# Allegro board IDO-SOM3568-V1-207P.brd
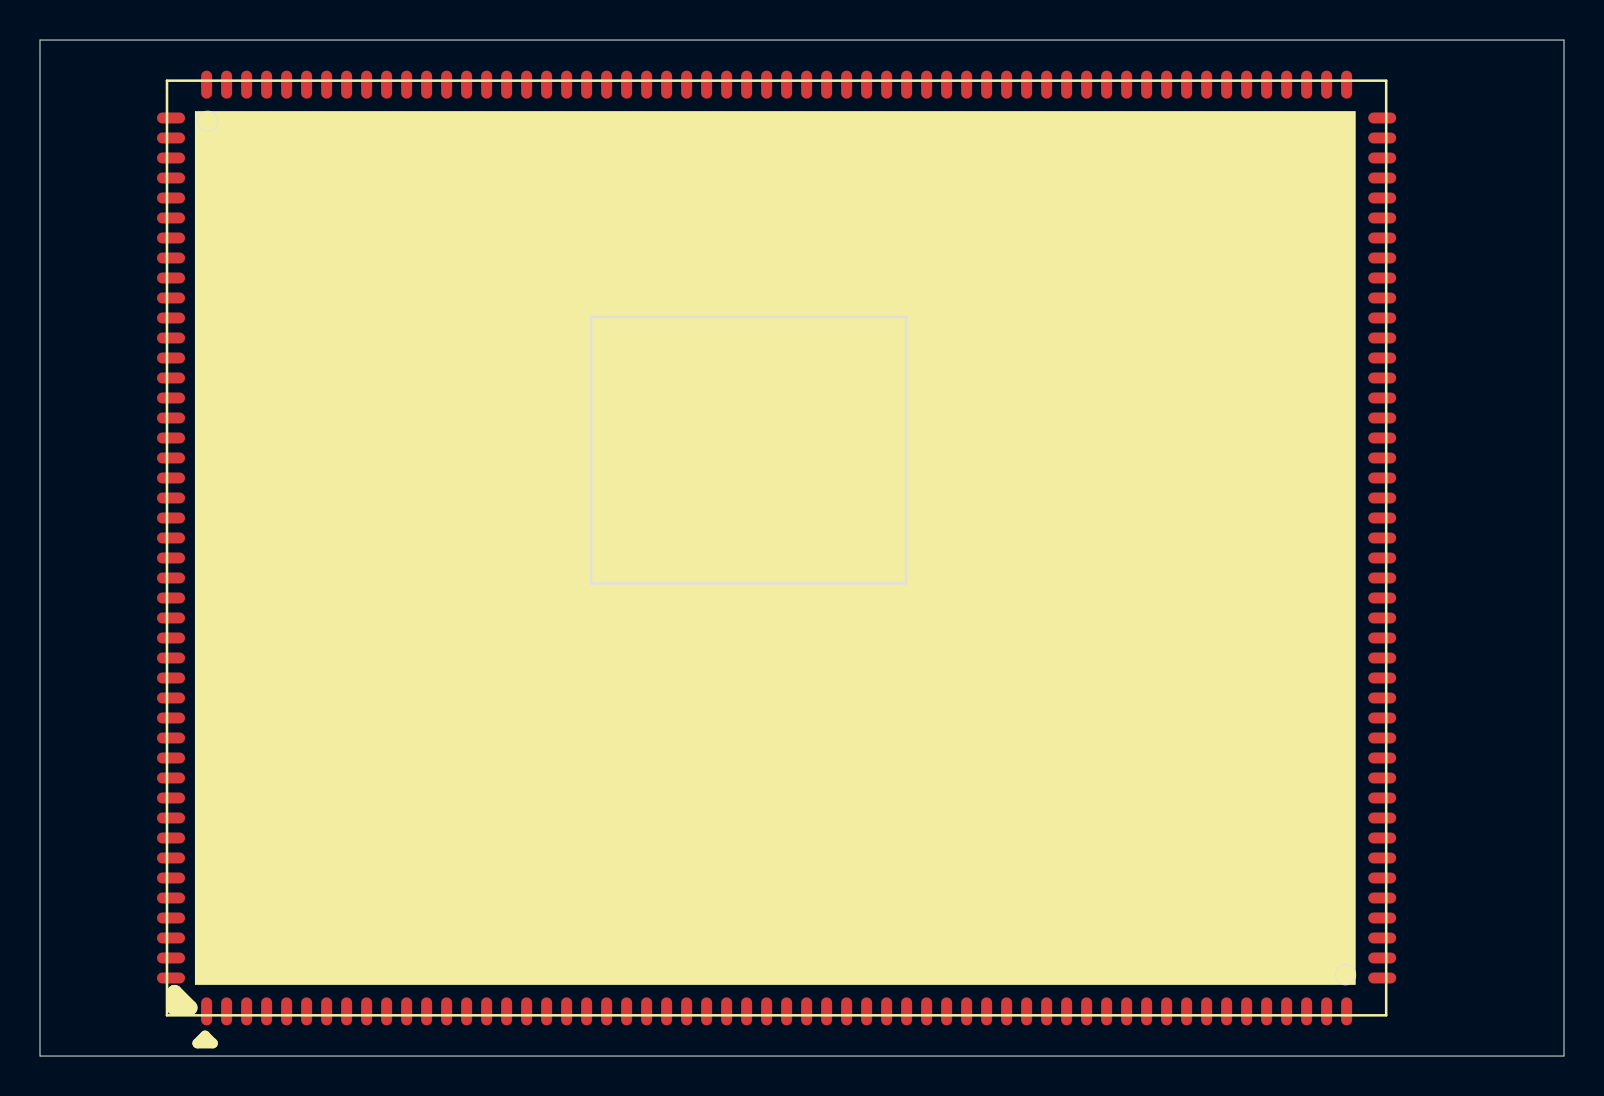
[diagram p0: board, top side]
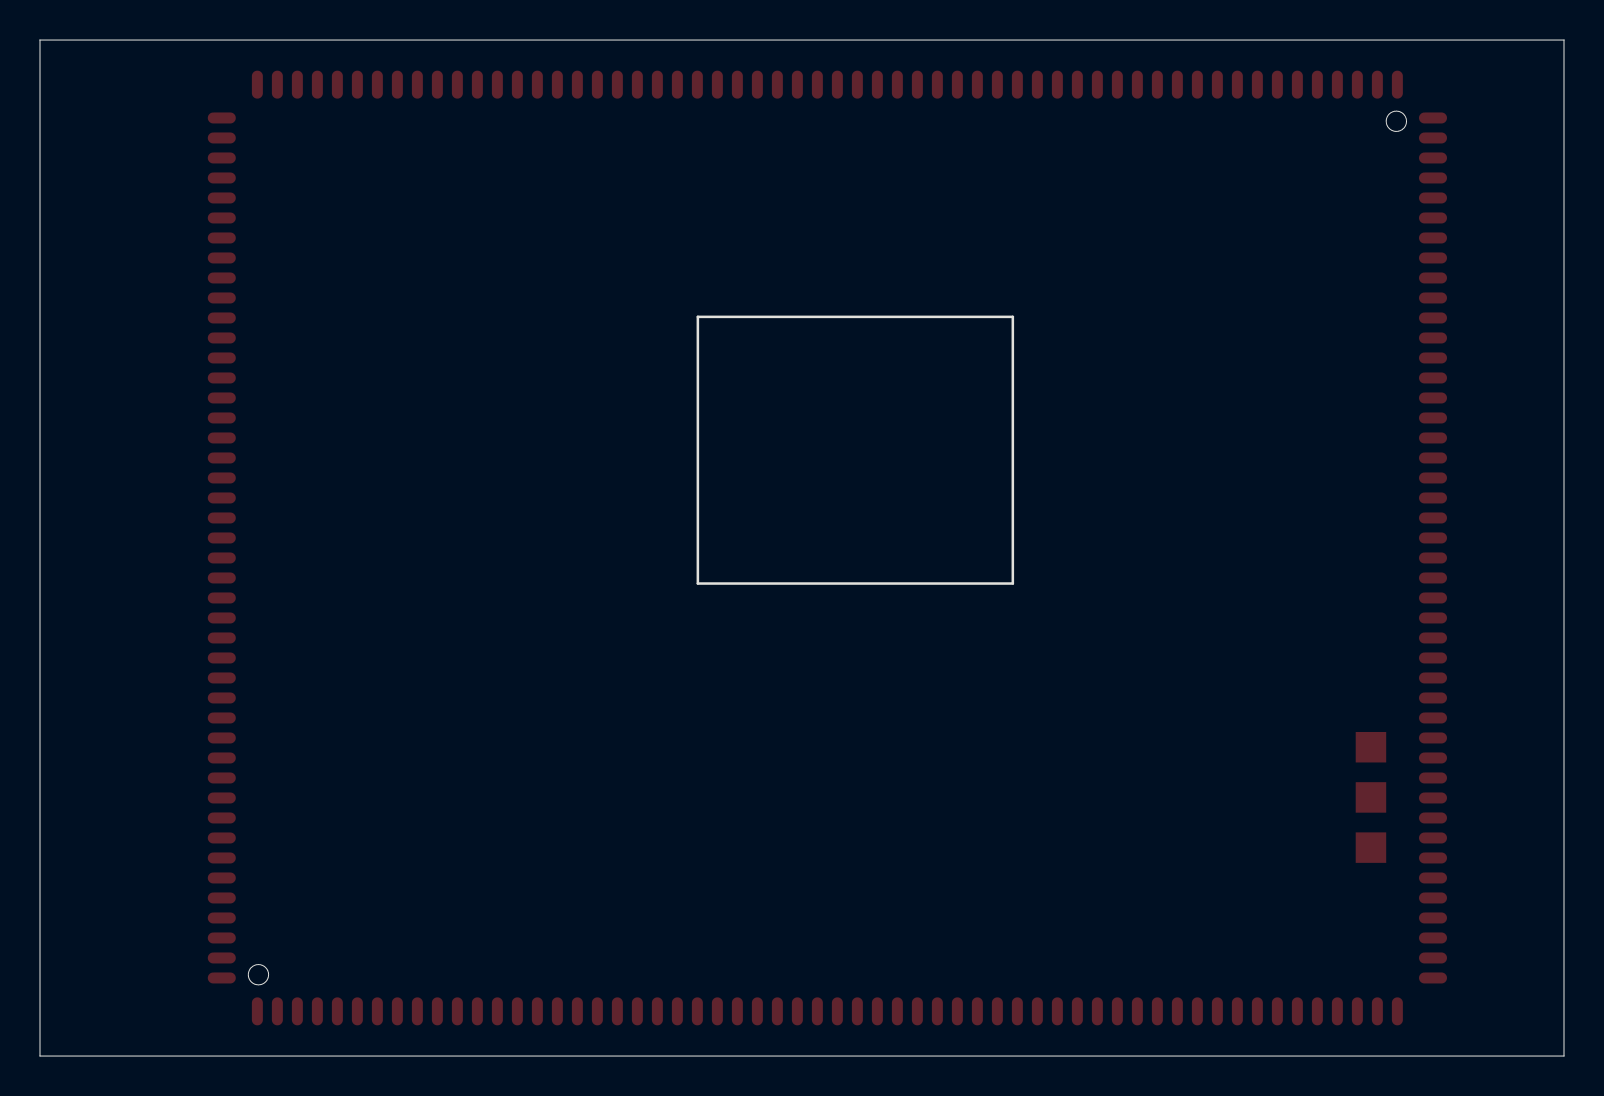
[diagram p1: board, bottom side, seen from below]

Outline 76.2 x 50.8 mm; copper layers: TOP, VCC, GND, BOTTOM. Coordinates in mm from the lower left corner of the outline.
Outline path: 0,50.8 0,0 76.2,0 76.2,50.8 0,50.8

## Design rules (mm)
net group DIFFPAIR0: nets HDMI_TX_D2N HDMI_TX_D2P
net group DIFFPAIR1: nets HDMI_TX_D2N_ HDMI_TX_D2P_
net group DIFFPAIR2: nets HDMI_TX_D1N_ HDMI_TX_D1P_
net group DIFFPAIR3: nets HDMI_TX_D1N HDMI_TX_D1P
net group DIFFPAIR4: nets HDMI_TX_D0N_ HDMI_TX_D0P_
net group DIFFPAIR5: nets HDMI_TX_D0N HDMI_TX_D0P
net group DIFFPAIR6: nets HDMI_TX_CLKN_ HDMI_TX_CLKP_
net group DIFFPAIR7: nets HDMI_TX_CLKN HDMI_TX_CLKP
net group DIFFPAIR8: nets USB2_HOST3_DM_ USB2_HOST3_DP_
net group DIFFPAIR9: nets FE2.1_DM1_ FE2.1_DP1_
net group DIFFPAIR10: nets FE2.1_DM1 FE2.1_DP1
net group DIFFPAIR11: nets USB2_HOST3_DM USB2_HOST3_DP
net group DIFFPAIR12: nets FE2.1_DM2_ FE2.1_DP2_
net group DIFFPAIR13: nets FE2.1_DM3_ FE2.1_DP3_
net group DIFFPAIR14: nets FE2.1_DM2 FE2.1_DP2
net group DIFFPAIR15: nets FE2.1_DM3 FE2.1_DP3
net group DIFFPAIR16: nets LVDS0_D0N LVDS0_D0P
net group DIFFPAIR17: nets LVDS0_D1N LVDS0_D1P
net group DIFFPAIR18: nets LVDS0_D2N LVDS0_D2P
net group DIFFPAIR19: nets LVDS0_CLKN LVDS0_CLKP
net group DIFFPAIR20: nets LVDS0_D3N LVDS0_D3P
net group DIFFPAIR21: nets LVDS1_D0N LVDS1_D0P
net group DIFFPAIR22: nets LVDS1_D1N LVDS1_D1P
net group DIFFPAIR23: nets LVDS1_D2N LVDS1_D2P
net group DIFFPAIR24: nets LVDS1_CLKN LVDS1_CLKP
net group DIFFPAIR25: nets LVDS1_D3N LVDS1_D3P
net group DIFFPAIR26: nets EDP_TX_D3N EDP_TX_D3P
net group DIFFPAIR27: nets EDP_TX_D3N_ EDP_TX_D3P_
net group DIFFPAIR28: nets EDP_TX_AUXN EDP_TX_AUXP
net group DIFFPAIR29: nets EDP_TX_AUXN_ EDP_TX_AUXP_
net group DIFFPAIR30: nets EDP_TX_D2N EDP_TX_D2P
net group DIFFPAIR31: nets EDP_TX_D2N_ EDP_TX_D2P_
net group DIFFPAIR32: nets EDP_TX_D1N EDP_TX_D1P
net group DIFFPAIR33: nets EDP_TX_D1N_ EDP_TX_D1P_
net group DIFFPAIR34: nets EDP_TX_D0N EDP_TX_D0P
net group DIFFPAIR35: nets EDP_TX_D0N_ EDP_TX_D0P_
net group DIFFPAIR36: nets USB3_HOST1_SSRXN_ USB3_HOST1_SSRXP_
net group DIFFPAIR37: nets USB3_HOST1_DM_ USB3_HOST1_DP_
net group DIFFPAIR38: nets USB3_OTG0_DM_ USB3_OTG0_DP_
net group DIFFPAIR39: nets USB3_OTG0_SSTXN_ USB3_OTG0_SSTXP_
net group DIFFPAIR40: nets USB3_HOST1_SSTXN_ USB3_HOST1_SSTXP_
net group DIFFPAIR41: nets USB3_HOST1_SSTXN USB3_HOST1_SSTXP
net group DIFFPAIR42: nets SATA1_TXN SATA1_TXP
net group DIFFPAIR43: nets USB3_OTG0_SSTXN USB3_OTG0_SSTXP
net group DIFFPAIR44: nets USB3_OTG0_DM USB3_OTG0_DP
net group DIFFPAIR45: nets USB3_HOST1_DM USB3_HOST1_DP
net group DIFFPAIR46: nets SATA1_RXN SATA1_RXP
net group DIFFPAIR47: nets USB3_HOST1_SSRXN USB3_HOST1_SSRXP
net group DIFFPAIR48: nets USB3_OTG0_SSRXN_ USB3_OTG0_SSRXP_
net group DIFFPAIR49: nets USB3_OTG0_SSRXN USB3_OTG0_SSRXP
net group DIFFPAIR50: nets FE2.1_DM5_ FE2.1_DP5_
net group DIFFPAIR51: nets FE2.1_DM5 FE2.1_DP5
net group DIFFPAIR52: nets FE2.1_DM6_ FE2.1_DP6_
net group DIFFPAIR53: nets FE2.1_DM6 FE2.1_DP6
net group DIFFPAIR54: nets FE2.1_DM4_ FE2.1_DP4_
net group DIFFPAIR55: nets FE2.1_DM4 FE2.1_DP4
net group DIFFPAIR56: nets MIPI_DSI_TX0_D3N_ MIPI_DSI_TX0_D3P_
net group DIFFPAIR57: nets MIPI_DSI_TX0_D2N_ MIPI_DSI_TX0_D2P_
net group DIFFPAIR58: nets MIPI_DSI_TX0_D3N MIPI_DSI_TX0_D3P
net group DIFFPAIR59: nets MIPI_DSI_TX0_D2N MIPI_DSI_TX0_D2P
net group DIFFPAIR60: nets MIPI_DSI_TX0_CLKN_ MIPI_DSI_TX0_CLKP_
net group DIFFPAIR61: nets MIPI_DSI_TX0_D1N_ MIPI_DSI_TX0_D1P_
net group DIFFPAIR62: nets MIPI_DSI_TX0_D1N MIPI_DSI_TX0_D1P
net group DIFFPAIR63: nets MIPI_DSI_TX0_CLKN MIPI_DSI_TX0_CLKP
net group DIFFPAIR64: nets MIPI_DSI_TX1_D3N MIPI_DSI_TX1_D3P
net group DIFFPAIR65: nets MIPI_DSI_TX1_D2N MIPI_DSI_TX1_D2P
net group DIFFPAIR66: nets MIPI_DSI_TX1_CLKN MIPI_DSI_TX1_CLKP
net group DIFFPAIR67: nets MIPI_DSI_TX1_D1N MIPI_DSI_TX1_D1P
net group DIFFPAIR68: nets MIPI_DSI_TX1_D0N MIPI_DSI_TX1_D0P
net group DIFFPAIR69: nets MIPI_DSI_TX0_D0N_ MIPI_DSI_TX0_D0P_
net group DIFFPAIR70: nets MIPI_DSI_TX0_D0N MIPI_DSI_TX0_D0P
net group DIFFPAIR71: nets USB2_HOST2_DM USB2_HOST2_DP
net group DIFFPAIR72: nets FE2.1_DM0 FE2.1_DP0
net group DIFFPAIR73: nets PCIE20_TXN PCIE20_TXP
net group DIFFPAIR74: nets PCIE20_RXN PCIE20_RXP
net group DIFFPAIR75: nets PCIE20_REFCLKN PCIE20_REFCLKP
net group DIFFPAIR76: nets PHY0_MDI3+ PHY0_MDI3-
net group DIFFPAIR77: nets PHY0_MDI2+ PHY0_MDI2-
net group DIFFPAIR78: nets PHY0_MDI1+ PHY0_MDI1-
net group DIFFPAIR79: nets LAN0_B+ LAN0_B-
net group DIFFPAIR80: nets LAN0_C+ LAN0_C-
net group DIFFPAIR81: nets LAN0_D+ LAN0_D-
net group DIFFPAIR82: nets LAN0_A+ LAN0_A-
net group DIFFPAIR83: nets PHY0_MDI0+ PHY0_MDI0-
net group DIFFPAIR84: nets PHY1_MDI0+ PHY1_MDI0-
net group DIFFPAIR85: nets LAN1_A+ LAN1_A-
net group DIFFPAIR86: nets LAN1_B+ LAN1_B-
net group DIFFPAIR87: nets PHY1_MDI1+ PHY1_MDI1-
net group DIFFPAIR88: nets LAN1_C+ LAN1_C-
net group DIFFPAIR89: nets PHY1_MDI2+ PHY1_MDI2-
net group DIFFPAIR90: nets PHY1_MDI3+ PHY1_MDI3-
net group DIFFPAIR91: nets LAN1_D+ LAN1_D-
net group DIFFPAIR92: nets FE2.1_DM7 FE2.1_DP7
net group DIFFPAIR93: nets FE2.1_DM7_ FE2.1_DP7_
net group DIFFPAIR96: nets REFCLKN_ REFCLKP_
net group DIFFPAIR97: nets VOLN VOLP
net group DIFFPAIR98: nets VORN VORP
net group DIFFPAIR99: nets MIPI_CSI_RX_D0N MIPI_CSI_RX_D0P
net group DIFFPAIR100: nets MIPI_CSI_RX_D1N MIPI_CSI_RX_D1P
net group DIFFPAIR101: nets MIPI_CSI_RX_D2N MIPI_CSI_RX_D2P
net group DIFFPAIR102: nets MIPI_CSI_RX_D3N MIPI_CSI_RX_D3P
net group DIFFPAIR103: nets MIPI_CSI_RX_CLK0N MIPI_CSI_RX_CLK0P
net group DIFFPAIR104: nets MIPI_CSI_D0N MIPI_CSI_D0P
net group DIFFPAIR105: nets MIPI_CSI_D1N MIPI_CSI_D1P
net group DIFFPAIR106: nets MIPI_CSI_D2N MIPI_CSI_D2P
net group DIFFPAIR107: nets MIPI_CSI_D3N MIPI_CSI_D3P
net group DIFFPAIR108: nets MIPI_CSI_CLKN MIPI_CSI_CLKP
net group DIFFPAIR109: nets PCIE20_RXN_ PCIE20_RXP_
net group DIFFPAIR110: nets PCIE20_TXN_ PCIE20_TXP_
net group PWR-20: nets VDD_RTC
net group SD-12: nets SD_CMD SD_D0 SD_D1 SD_D2 SD_D3

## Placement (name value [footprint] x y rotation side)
M5  IDO-SOM3568  [SOM3568-204P]  5.84 1.52 0 top

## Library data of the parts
M5 = MODE-204P_2

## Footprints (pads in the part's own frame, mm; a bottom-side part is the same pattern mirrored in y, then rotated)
SOM3568-204P
  oval 0.55x1.4 smd: 1(2.489,0.708) 2(3.489,0.708) 3(4.489,0.708) 4(5.489,0.708) 5(6.489,0.708) 6(7.489,0.708) 7(8.489,0.708) 8(9.489,0.708) 9(10.489,0.708) 10(11.489,0.708) 11(12.489,0.708) 12(13.489,0.708) 13(14.489,0.708) 14(15.489,0.708) 15(16.489,0.708) 16(17.489,0.708) 17(18.489,0.708) 18(19.489,0.708) 19(20.489,0.708) 20(21.489,0.708) 21(22.489,0.708) 22(23.489,0.708) 23(24.489,0.708) 24(25.489,0.708) 25(26.489,0.708) 26(27.489,0.708) 27(28.489,0.708) 28(29.489,0.708) 29(30.489,0.708) 30(31.489,0.708) 31(32.489,0.708) 32(33.489,0.708) 33(34.489,0.708) 34(35.489,0.708) 35(36.489,0.708) 36(37.489,0.708) 37(38.489,0.708) 38(39.489,0.708) 39(40.489,0.708) 40(41.489,0.708) 41(42.489,0.708) 42(43.489,0.708) 43(44.489,0.708) 44(45.489,0.708) 45(46.489,0.708) 46(47.489,0.708) 47(48.489,0.708) 48(49.489,0.708) 49(50.489,0.708) 50(51.489,0.708) 51(52.489,0.708) 52(53.489,0.708) 53(54.489,0.708) 54(55.489,0.708) 55(56.489,0.708) 56(57.489,0.708) 57(58.489,0.708) 58(59.489,0.708) 103(59.489,47.044) 104(58.489,47.044) 105(57.489,47.044) 106(56.489,47.044) 107(55.489,47.044) 108(54.489,47.044) 109(53.489,47.044) 110(52.489,47.044) 111(51.489,47.044) 112(50.489,47.044) 113(49.489,47.044) 114(48.489,47.044) 115(47.489,47.044) 116(46.489,47.044) 117(45.489,47.044) 118(44.489,47.044) 119(43.489,47.044) 120(42.489,47.044) 121(41.489,47.044) 122(40.489,47.044) 123(39.489,47.044) 124(38.489,47.044) 125(37.489,47.044) 126(36.489,47.044) 127(35.489,47.044) 128(34.489,47.044) 129(33.489,47.044) 130(32.489,47.044) 131(31.489,47.044) 132(30.489,47.044) 133(29.489,47.044) 134(28.489,47.044) 135(27.489,47.044) 136(26.489,47.044) 137(25.489,47.044) 138(24.489,47.044) 139(23.489,47.044) 140(22.489,47.044) 141(21.489,47.044) 142(20.489,47.044) 143(19.489,47.044) 144(18.489,47.044) 145(17.489,47.044) 146(16.489,47.044) 147(15.489,47.044) 148(14.489,47.044) 149(13.489,47.044) 150(12.489,47.044) 151(11.489,47.044) 152(10.489,47.044) 153(9.489,47.044) 154(8.489,47.044) 155(7.489,47.044) 156(6.489,47.044) 157(5.489,47.044) 158(4.489,47.044) 159(3.489,47.044) 160(2.489,47.044)
  oval 1.4x0.55 smd: 59(61.268,2.377) 60(61.268,3.377) 61(61.268,4.377) 62(61.268,5.377) 63(61.268,6.377) 64(61.268,7.377) 65(61.268,8.377) 66(61.268,9.377) 67(61.268,10.377) 68(61.268,11.377) 69(61.268,12.377) 70(61.268,13.377) 71(61.268,14.377) 72(61.268,15.377) 73(61.268,16.377) 74(61.268,17.377) 75(61.268,18.377) 76(61.268,19.377) 77(61.268,20.377) 78(61.268,21.377) 79(61.268,22.377) 80(61.268,23.377) 81(61.268,24.377) 82(61.268,25.377) 83(61.268,26.377) 84(61.268,27.377) 85(61.268,28.377) 86(61.268,29.377) 87(61.268,30.377) 88(61.268,31.377) 89(61.268,32.377) 90(61.268,33.377) 91(61.268,34.377) 92(61.268,35.377) 93(61.268,36.377) 94(61.268,37.377) 95(61.268,38.377) 96(61.268,39.377) 97(61.268,40.377) 98(61.268,41.377) 99(61.268,42.377) 100(61.268,43.377) 101(61.268,44.377) 102(61.268,45.377) 161(0.708,45.377) 162(0.708,44.377) 163(0.708,43.377) 164(0.708,42.377) 165(0.708,41.377) 166(0.708,40.377) 167(0.708,39.377) 168(0.708,38.377) 169(0.708,37.377) 170(0.708,36.377) 171(0.708,35.377) 172(0.708,34.377) 173(0.708,33.377) 174(0.708,32.377) 175(0.708,31.377) 176(0.708,30.377) 177(0.708,29.377) 178(0.708,28.377) 179(0.708,27.377) 180(0.708,26.377) 181(0.708,25.377) 182(0.708,24.377) 183(0.708,23.377) 184(0.708,22.377) 185(0.708,21.377) 186(0.708,20.377) 187(0.708,19.377) 188(0.708,18.377) 189(0.708,17.377) 190(0.708,16.377) 191(0.708,15.377) 192(0.708,14.377) 193(0.708,13.377) 194(0.708,12.377) 195(0.708,11.377) 196(0.708,10.377) 197(0.708,9.377) 198(0.708,8.377) 199(0.708,7.377) 200(0.708,6.377) 201(0.708,5.377) 202(0.708,4.377) 203(0.708,3.377) 204(0.708,2.377)
  rect 1.524x1.524 smd: 205(3.81,8.895) 206(3.81,11.405) 207(3.81,13.914)

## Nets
GND: M5.4(GND1) M5.5(GND2) M5.14(GND3) M5.38(GND4) M5.98(GND5) M5.105(GND6) M5.127(GND7) M5.152(GND8) M5.179(GND9) M5.194(GND10)
VCC3V3_SD: M5.69(VCC3V3_SD)
VCC5V0_SYS: M5.1(VCC5V0_RTC) M5.2(VCC5V0_SYS1) M5.3(VCC5V0_SYS2)
VCC_1V8: M5.103(VCC_1V8)
VCC_3V3: M5.104(VCC_3V3)
4G_5G_RESET_GPIO3_A4: M5.123(LCDC_D11/VOP_BT1120_D3/GMAC1_RX)
BT_REG_ON_H_GPIO3_A7: M5.120(LCDC_D14/VOP_BT1120_D5/GMAC1_RX)
BT_WAKE_HOST_H_GPIO3_A1: M5.126(LCDC_D8/VOP_BT1120_D0/SPI1_CS0_)
CAN1_RX_M0: M5.36(I2C3_SDA_M0/UART3_RX_M0/CAN1_RX)
CAN1_TX_M0: M5.37(I2C3_SCL_M0/UART3_TX_M0/CAN1_TX)
CAN2_RX_M0: M5.75(I2C2_SDA_M1/EBC_GDSP/CAN2_RX_M0)
CAN2_TX_M0: M5.74(I2C2_SCL_M1/EBC_SDSHR/CAN2_TX_M)
CIF_CLKOUT_SOC: M5.71(CIF_CLKOUT/EBC_GDCLK/PWM11_IR_M)
CIF_RST_GPIO3_A3: M5.124(LCDC_D10/VOP_BT1120_D2/GMAC1_TX)
EDP_HPDIN_M1: M5.21(PWM3_IR/EDP_HPDIN_M1/PCIE30X1_W)
EDP_PWM4: M5.22(PWM4/VOP_PWM_M0/PCIE30X1_PERSTN)
EDP_TX_AUXN: M5.197(EDP_TX_AUXN)
EDP_TX_AUXP: M5.198(EDP_TX_AUXP)
EDP_TX_D0N: M5.203(EDP_TX_D0N)
EDP_TX_D0P: M5.204(EDP_TX_D0P)
EDP_TX_D1N: M5.201(EDP_TX_D1N)
EDP_TX_D1P: M5.202(EDP_TX_D1P)
EDP_TX_D2N: M5.199(EDP_TX_D2N)
EDP_TX_D2P: M5.200(EDP_TX_D2P)
EDP_TX_D3N: M5.195(EDP_TX_D3N)
EDP_TX_D3P: M5.196(EDP_TX_D3P)
EXT_EN: M5.7(EXT_EN)
GMAC0_INT/PMEB_GPIO3_B0: M5.119(LCDC_D15/VOP_BT1120_D6/ETH1_REF)
GMAC0_MCLKINOUT: M5.54(I2S2_SCLK_TX_M0/GMAC0_MCLKINOUT)
GMAC0_MDC: M5.55(I2S2_LRCK_TX_M0/GMAC0_MDC/UART9)
GMAC0_MDIO: M5.56(I2S2_SDO_M0/GMAC0_MDIO/UART9_CT)
GMAC0_RSTN_GPIO3_A5: M5.122(LCDC_D12/VOP_BT1120_D4/GMAC1_RX)
GMAC0_RXCLK: M5.41(SDMMC1_D2/GMAC0_RXCLK/UART7_RX_)
GMAC0_RXD0: M5.50(GMAC0_RXD0/UART1_CTSN_M0/SPI1_M)
GMAC0_RXD1: M5.51(I2S2_SCLK_RX_M0/GMAC0_RXD1/UART)
GMAC0_RXD2: M5.39(SDMMC1_D0/GMAC0_RXD2/UART6_RX_M)
GMAC0_RXD3: M5.40(SDMMC1_D1/GMAC0_RXD3/UART6_TX_M)
GMAC0_RXDV_CRS: M5.52(I2S2_LRCK_RX_M0/GMAC0_RXDV_CRS/)
GMAC0_TXCLK: M5.44(SDMMC1_CLK/GMAC0_TXCLK/UART9_TX)
GMAC0_TXD0: M5.47(GMAC0_TXD0/UART1_RX_M0/GPIO2_B3)
GMAC0_TXD1: M5.48(GMAC0_TXD1/UART1_TX_M0/GPIO2_B4)
GMAC0_TXD2: M5.42(SDMMC1_D3/GMAC0_TXD2/UART7_TX_M)
GMAC0_TXD3: M5.43(SDMMC1_CMD/GMAC0_TXD3/UART9_RX_)
GMAC0_TXEN: M5.49(GMAC0_TXEN/UART1_RTSN_M0/SPI1_C)
GMAC1_INT/PMEB_GPIO3_C1: M5.110(LCDC_HSYNC/VOP_BT1120_D13/SPI1_)
GMAC1_MCLKINOUT_M1: M5.70(CIF_CLKIN/EBC_SDCLK/GMAC1_MCLKI)
GMAC1_MDC_M1: M5.73(CIF_HREF/EBC_SDLE/GMAC1_MDC_M1/)
GMAC1_MDIO_M1: M5.72(CIF_VSYNC/EBC_SDOE/GMAC1_MDIO_M)
GMAC1_RSTN_GPIO3_A6: M5.121(LCDC_D13/VOP_BT1120_CLK/GMAC1_T)
GMAC1_RXCLK_M1: M5.84(CIF_D13/EBC_SDDO13/GMAC1_RXCLK_)
GMAC1_RXD0_M1: M5.80(CAM_CLKOUT0/EBC_SDCE1/GMAC1_RXD)
GMAC1_RXD1_M1: M5.79(CAM_CLKOUT1/EBC_SDCE2/GMAC1_RXD)
GMAC1_RXD2_M1: M5.86(CIF_D11/EBC_SDDO11/GMAC1_RXD2_M)
GMAC1_RXD3_M1: M5.85(CIF_D12/EBC_SDDO12/GMAC1_RXD3_M)
GMAC1_RXDV_CRS_M1: M5.78(ISP_PRELIGHT_TRIG/EBC_SDCE3/GMA)
GMAC1_TXCLK_M1: M5.87(CIF_D10/EBC_SDDO10/GMAC1_TXCLK_)
GMAC1_TXD0_M1: M5.83(CIF_D14/EBC_SDDO14/GMAC1_TXD0_M)
GMAC1_TXD1_M1: M5.82(CIF_D15/EBC_SDDO15/GMAC1_TXD1_M)
GMAC1_TXD2_M1: M5.89(CIF_D8/EBC_SDDO8/GMAC1_TXD2_M1/)
GMAC1_TXD3_M1: M5.88(CIF_D9/EBC_SDDO9/GMAC1_TXD3_M1/)
GMAC1_TXEN_M1: M5.81(ISP_FLASHTRIGOUT/EBC_SDCE0/GMAC)
HDMI_TX_CLKN: M5.153(HDMI_TX_CLKN)
HDMI_TX_CLKP: M5.154(HDMI_TX_CLKP)
HDMI_TX_D0N: M5.155(HDMI_TX_D0N)
HDMI_TX_D0P: M5.156(HDMI_TX_D0P)
HDMI_TX_D1N: M5.157(HDMI_TX_D1N)
HDMI_TX_D1P: M5.158(HDMI_TX_D1P)
HDMI_TX_D2N: M5.159(HDMI_TX_D2N)
HDMI_TX_D2P: M5.160(HDMI_TX_D2P)
HDMI_TX_HPDIN: M5.148(HDMI_TX_HPDIN)
HDMITX_CEC_M0: M5.151(HDMITX_CEC_M0/SPI3_CS1_M1/GPIO4)
HOST_WAKE_BT_H_GPIO3_A2: M5.125(LCDC_D9/VOP_BT1120_D1/GMAC1_TXD)
HP_DET_H_GPIO0_C5: M5.24(PWM6/SPI0_MISO_M0/PCIE30X2_WAKE)
HP_SNS: M5.10(HP_SNS)
HPL_OUT: M5.9(HPL_OUT)
HPR_OUT: M5.11(HPR_OUT)
I2C1_SCL: M5.32(I2C1_SCL/CAN0_TX_M0/PCIE30X1_BU)
I2C1_SDA: M5.33(I2C1_SDA/CAN0_RX_M0/PCIE20_BUTT)
I2C2_SCL_M0: M5.34(I2C2_SCL_M0/SPI0_CLK_M0/PCIE20_)
I2C2_SDA_M0: M5.35(I2C2_SDA_M0/SPI0_MOSI_M0/PCIE20)
I2C3_SCL_M1: M5.114(LCDC_D20/VOP_BT1120_D11/GMAC1_T)
I2C3_SDA_M1: M5.113(LCDC_D21/VOP_BT1120_D12/GMAC1_T)
I2C4_SCL_M0: M5.76(I2C4_SCL_M0/EBC_GDOE/ETH1_REFCL)
I2C4_SDA_M0: M5.77(I2C4_SDA_M0/EBC_VCOM/GMAC1_RXER)
I2C5_SCL-HDMI: M5.150(HDMITX_SCL/I2C5_SCL_M1/GPIO4_C7)
I2C5_SDA-HDMI: M5.149(HDMITX_SDA/I2C5_SDA_M1/GPIO4_D0)
LVDS_PWM5: M5.23(PWM5/SPI0_CS1_M0/UART0_RTSN/GPI)
MIC1_INN: M5.13(MIC1_INN)
MIC1_INP: M5.12(MIC1_INP)
MIPI_CAM0_PDN_L_GPIO2_C1: M5.53(I2S2_MCLK_M0/ETH0_REFCLKO_25M/U)
MIPI_CSI_RX_CLK0N: M5.170(MIPI_CSI_RX_CLK0N/PCIE30_REFCLK)
MIPI_CSI_RX_CLK0P: M5.169(MIPI_CSI_RX_CLK0P/PCIE30_REFCLK)
MIPI_CSI_RX_CLK1N: M5.172(MIPI_CSI_RX_CLK1N)
MIPI_CSI_RX_CLK1P: M5.171(MIPI_CSI_RX_CLK1P)
MIPI_CSI_RX_D0N: M5.162(MIPI_CSI_RX_D0N/PCIE30_TX0N)
MIPI_CSI_RX_D0P: M5.161(MIPI_CSI_RX_D0P/PCIE30_TX0P)
MIPI_CSI_RX_D1N: M5.164(MIPI_CSI_RX_D1N/PCIE30_TX1N)
MIPI_CSI_RX_D1P: M5.163(MIPI_CSI_RX_D1P/PCIE30_TX1P)
MIPI_CSI_RX_D2N: M5.166(MIPI_CSI_RX_D2N/PCIE30_RX0N)
MIPI_CSI_RX_D2P: M5.165(MIPI_CSI_RX_D2P/PCIE30_RX0P)
MIPI_CSI_RX_D3N: M5.168(MIPI_CSI_RX_D3N/PCIE30_RX1N)
MIPI_CSI_RX_D3P: M5.167(MIPI_CSI_RX_D3P/PCIE30_RX1P)
MIPI_DSI_TX0_CLKN: M5.142(MIPI_DSI_TX0_CLKN/LVDS_TX0_CLKN)
MIPI_DSI_TX0_CLKP: M5.143(MIPI_DSI_TX0_CLKP/LVDS_TX0_CLKP)
MIPI_DSI_TX0_D0N: M5.146(MIPI_DSI_TX0_D0N/LVDS_TX0_D0N)
MIPI_DSI_TX0_D0P: M5.147(MIPI_DSI_TX0_D0P/LVDS_TX0_D0P)
MIPI_DSI_TX0_D1N: M5.144(MIPI_DSI_TX0_D1N/LVDS_TX0_D1N)
MIPI_DSI_TX0_D1P: M5.145(MIPI_DSI_TX0_D1P/LVDS_TX0_D1P)
MIPI_DSI_TX0_D2N: M5.140(MIPI_DSI_TX0_D2N/LVDS_TX0_D2N)
MIPI_DSI_TX0_D2P: M5.141(MIPI_DSI_TX0_D2P/LVDS_TX0_D2P)
MIPI_DSI_TX0_D3N: M5.138(MIPI_DSI_TX0_D3N/LVDS_TX0_D3N)
MIPI_DSI_TX0_D3P: M5.139(MIPI_DSI_TX0_D3P/LVDS_TX0_D3P)
MIPI_DSI_TX1_CLKN: M5.132(MIPI_DSI_TX1_CLKN)
MIPI_DSI_TX1_CLKP: M5.133(MIPI_DSI_TX1_CLKP)
MIPI_DSI_TX1_D0N: M5.136(MIPI_DSI_TX1_D0N)
MIPI_DSI_TX1_D0P: M5.137(MIPI_DSI_TX1_D0P)
MIPI_DSI_TX1_D1N: M5.134(MIPI_DSI_TX1_D1N)
MIPI_DSI_TX1_D1P: M5.135(MIPI_DSI_TX1_D1P)
MIPI_DSI_TX1_D2N: M5.130(MIPI_DSI_TX1_D2N)
MIPI_DSI_TX1_D2P: M5.131(MIPI_DSI_TX1_D2P)
MIPI_DSI_TX1_D3N: M5.128(MIPI_DSI_TX1_D3N)
MIPI_DSI_TX1_D3P: M5.129(MIPI_DSI_TX1_D3P)
PCA9539_INT_GPIO4_C4: M5.29(EDP_HPDIN_M0/SPDIF_TX_M2/SATA2_)
PCIE20_REFCLKN: M5.178(PCIE20_REFCLKN)
PCIE20_REFCLKP: M5.177(PCIE20_REFCLKP)
PCIE20_RXN: M5.176(PCIE20_RXN/SATA2_RXN/QSGMII_RXN)
PCIE20_RXP: M5.175(PCIE20_RXP/SATA2_RXP/QSGMII_RXP)
PCIE20_TXN: M5.174(PCIE20_TXN/SATA2_TXN/QSGMII_TXN)
PCIE20_TXP: M5.173(PCIE20_TXP/SATA2_TXP/QSGMII_TXP)
PWM7_IR: M5.25(PWM7_IR/SPI0_CS0_M0/PCIE30X2_PE)
RK809_PWRON: M5.8(RK809_PWRON)
RK809_VDC: M5.6(RK809_VDC)
SARADC_VIN0_KEY/RECOVERY: M5.15(SARADC_VIN0_KEY/RECOVERY)
SARADC_VIN2_HP_HOOK: M5.16(SARADC_VIN2_HP_HOOK)
SARADC_VIN4: M5.17(SARADC_VIN4)
SARADC_VIN5: M5.18(SARADC_VIN5)
SDMMC0_CLK: M5.63(SDMMC0_CLK/TEST_CLKOUT/UART5_TX)
SDMMC0_CMD: M5.64(SDMMC0_CMD/PWM10_M1/UART5_RX_M0)
SDMMC0_D0: M5.68(SDMMC0_D0/UART2_TX_M1/UART6_TX_)
SDMMC0_D1: M5.67(SDMMC0_D1/UART2_RX_M1/UART6_RX_)
SDMMC0_D2: M5.66(SDMMC0_D2/ARMJTAG_TCK/UART5_CTS)
SDMMC0_D3: M5.65(SDMMC0_D3/ARMJTAG_TMS/UART5_RTS)
SDMMC0_DET_L: M5.62(SDMMC0_DET/SATA_CP_DET/PCIE30X1)
SDMMC2_CLK_M0: M5.92(CIF_D5/EBC_SDDO5/SDMMC2_CLK_M0/)
SDMMC2_CMD_M0: M5.93(CIF_D4/EBC_SDDO4/SDMMC2_CMD_M0/)
SDMMC2_D0_M0: M5.97(CIF_D0/EBC_SDDO0/SDMMC2_D0_M0/I)
SDMMC2_D1_M0: M5.96(CIF_D1/EBC_SDDO1/SDMMC2_D1_M0/I)
SDMMC2_D2_M0: M5.95(CIF_D2/EBC_SDDO2/SDMMC2_D2_M0/I)
SDMMC2_D3_M0: M5.94(CIF_D3/EBC_SDDO3/SDMMC2_D3_M0/I)
SPI3_CLK_M1: M5.27(PWM14_M1/SPI3_CLK_M1/CAN1_RX_M1)
SPI3_CS0_M1: M5.31(PWM13_M1/SPI3_CS0_M1/SATA0_ACT_)
SPI3_MISO_M1: M5.30(PWM12_M1/SPI3_MISO_M1/SATA1_ACT)
SPI3_MOSI_M1: M5.28(PWM15_IR_M1/SPI3_MOSI_M1/CAN1_T)
SYS_LED_GPIO0_C7: M5.26(HDMITX_CEC_M1/PWM0_M1/UART0_CTS)
TP_INT_L_GPIO3_B4: M5.115(LCDC_D19/VOP_BT1120_D10/GMAC1_R)
TP_RST_L_GPIO3_B3: M5.116(LCDC_D18/VOP_BT1120_D9/GMAC1_RX)
UART0_RX: M5.19(PWM1_M0/GPUAVS/UART0_RX/GPIO0_C)
UART0_TX: M5.20(PWM2_M0/NPUAVS/UART0_TX/MCU_JTA)
UART2_RX_M0: M5.60(UART2_RX_M0/GPIO0_D0_U)
UART2_TX_M0: M5.59(UART2_TX_M0/GPIO0_D1_U)
UART3_RX_M1: M5.111(LCDC_D23/PWM13_M0/GMAC1_MCLKINO)
UART3_TX_M1: M5.112(LCDC_D22/PWM12_M0/GMAC1_TXEN_M0)
UART4_RX_M1: M5.118(LCDC_D16/VOP_BT1120_D7/GMAC1_RX)
UART4_TX_M1: M5.117(LCDC_D17/VOP_BT1120_D8/GMAC1_RX)
UART5_RX_M1: M5.108(LCDC_DEN/VOP_BT1120_D15/SPI1_CL)
UART5_TX_M1: M5.109(LCDC_VSYNC/VOP_BT1120_D14/SPI1_)
UART7_RX_M1: M5.106(PWM15_IR_M0/SPDIF_TX_M1/GMAC1_M)
UART7_TX_M1: M5.107(PWM14_M0/VOP_PWM_M1/GMAC1_MDC_M)
UART8_CTSN_M0: M5.46(SDMMC1_DET/I2C4_SCL_M1/UART8_CT)
UART8_RTSN_M0: M5.45(SDMMC1_PWREN/I2C4_SDA_M1/UART8_)
UART8_RX_M0: M5.58(CLK32K_OUT1/UART8_RX_M0/SPI1_CS)
UART8_TX_M0: M5.57(I2S2_SDI_M0/GMAC0_RXER/UART8_TX)
USB2_HOST2_DM: M5.99(USB2_HOST2_DM)
USB2_HOST2_DP: M5.100(USB2_HOST2_DP)
USB2_HOST3_DM: M5.101(USB2_HOST3_DM)
USB2_HOST3_DP: M5.102(USB2_HOST3_DP)
USB3_HOST1_DM: M5.182(USB3_HOST1_DM)
USB3_HOST1_DP: M5.183(USB3_HOST1_DP)
USB3_HOST1_SSRXN: M5.185(USB3_HOST1_SSRXN/SATA1_RXN/QSGM)
USB3_HOST1_SSRXP: M5.184(USB3_HOST1_SSRXP/SATA1_RXP/QSGM)
USB3_HOST1_SSTXN: M5.181(USB3_HOST1_SSTXN/SATA1_TXN/QSGM)
USB3_HOST1_SSTXP: M5.180(USB3_HOST1_SSTXP/SATA1_TXP/QSGM)
USB3_OTG0_DM: M5.188(USB3_OTG0_DM)
USB3_OTG0_DP: M5.189(USB3_OTG0_DP)
USB3_OTG0_ID: M5.193(USB3_OTG0_ID)
USB3_OTG0_SSRXN: M5.191(USB3_OTG0_SSRXN/SATA0_RXN)
USB3_OTG0_SSRXP: M5.190(USB3_OTG0_SSRXP/SATA0_RXP)
USB3_OTG0_SSTXN: M5.187(USB3_OTG0_SSTXN/SATA0_TXN)
USB3_OTG0_SSTXP: M5.186(USB3_OTG0_SSTXP/SATA0_TXP)
USB3_OTG0_VBUSDET: M5.192(USB3_OTG0_VBUSDET)
USB_OTG_PWREN_H: M5.61(SDMMC0_PWREN/SATA_MP_SWITCH/PCI)
WIFI_REG_ON_H_GPIO3_D4: M5.91(CIF_D6/EBC_SDDO6/SDMMC2_DET_M0/)
WIFI_WAKE_HOST_H_GPIO3_D5: M5.90(CIF_D7/EBC_SDDO7/SDMMC2_PWREN_M)

Pads without a net: M5 205 206 207
